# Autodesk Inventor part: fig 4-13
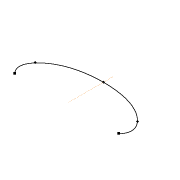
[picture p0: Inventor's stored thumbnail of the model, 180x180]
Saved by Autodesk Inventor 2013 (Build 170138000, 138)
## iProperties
Created: 2012-07
Part Number: fig 4-13
Material: Generic
Document SubType Name: Modeling
Designer: CADCIM
Density: 1 g/cm^3
Author: CADCIM
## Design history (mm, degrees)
sketch "Sketch1"
  geometry: L1 (0.121, 13.041)-(0.121, 1.483); L2 (-10.815, -1.576)-(-15.691, 3.573); L3 (-3.522, 10.439)-(3.764, 10.439); L4 (-14.873, 3.848)-(-11.149, 8.074); L5 (11.391, 8.074)-(15.115, 3.848); L6 (15.933, 3.573)-(11.057, -1.576); A1 r 5.401 centre (-9.332, 4.712) between (-14.53, 3.248) and (-11.076, -0.399); A2 r 30.439 centre (0.121, -20) between (3.022, 10.3) and (-2.78, 10.3); A3 r 7.63 centre (-7.286, 0.917) between (-11.348, 7.376) and (-14.205, 4.133); A4 r 7.63 centre (7.528, 0.917) between (14.447, 4.133) and (11.59, 7.376); A5 r 5.401 centre (9.574, 4.712) between (11.318, -0.399) and (14.772, 3.248); 5 further points
  constraints: 12 end point, 10 symmetric about line, 8 midpoint, 5 centre point, 5 point on circle, 1 vertical, 19 other
